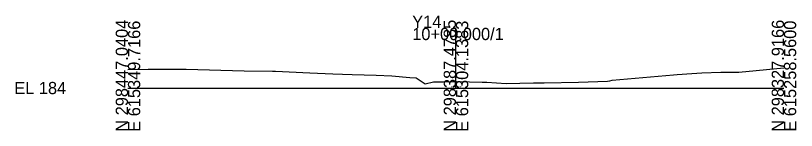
# Model space of a CAD drawing. Extents: x 517327 to 517505, y 114839 to 117370.
# Drawn here: x 517326.7 to 517505.2, y 114838.7 to 114864.9 of the extents above; entities that cross this region are included whole.
import ezdxf

# ---------------------------------------------------------------- set-up
doc = ezdxf.new("R2010")
doc.units = 0
for name, color, linetype in [('Exist XS Ground Line', 7, 'Continuous'), ('Old_Level_60', 7, 'Continuous'), ('Old_Level_63', 7, 'Continuous')]:
    doc.layers.add(name, color=color, linetype=linetype)

msp = doc.modelspace()

# ---------------------------------------------------------------- linework, layer by layer
at = {"layer": 'Exist XS Ground Line'}
for p, q in [((517492.08, 114851.95), (517502.36, 114852.95)), ((517352.36, 114852.6), (517357.02, 114852.65)), ((517357.02, 114852.65), (517362.06, 114852.68)), ((517362.06, 114852.68), (517365.68, 114852.65)), ((517365.68, 114852.65), (517378.94, 114852.27)), ((517378.94, 114852.27), (517385.42, 114852.23)), ((517385.42, 114852.23), (517386.07, 114852.21)), ((517386.07, 114852.21), (517393.92, 114851.84)), ((517393.92, 114851.84), (517399.21, 114851.6)), ((517399.21, 114851.6), (517403.62, 114851.45)), ((517403.62, 114851.45), (517409.1, 114851.27)), ((517409.1, 114851.27), (517412.73, 114851.13)), ((517412.73, 114851.13), (517416.78, 114850.77)), ((517463.07, 114850.13), (517477.08, 114851.37)), ((517477.08, 114851.37), (517477.97, 114851.48)), ((517477.97, 114851.48), (517481.33, 114851.66)), ((517481.33, 114851.66), (517483.55, 114851.84)), ((517483.55, 114851.84), (517487.91, 114851.99)), ((517487.91, 114851.99), (517492.08, 114851.95)), ((517416.78, 114850.77), (517418.29, 114850.66)), ((517418.29, 114850.66), (517418.7, 114850.38)), ((517418.7, 114850.38), (517420.33, 114849.35)), ((517420.33, 114849.35), (517422.2, 114849.8)), ((517422.2, 114849.8), (517424.46, 114849.77)), ((517424.46, 114849.77), (517427.51, 114849.84)), ((517427.51, 114849.84), (517430.48, 114849.76)), ((517430.48, 114849.76), (517433.36, 114849.71)), ((517433.36, 114849.71), (517433.71, 114849.68)), ((517433.71, 114849.68), (517434.4, 114849.66)), ((517434.4, 114849.66), (517438.83, 114849.36)), ((517438.83, 114849.36), (517445.1, 114849.53)), ((517445.1, 114849.53), (517446.59, 114849.55)), ((517446.59, 114849.55), (517447.51, 114849.51)), ((517447.51, 114849.51), (517455.41, 114849.72)), ((517455.41, 114849.72), (517461.98, 114849.95)), ((517461.98, 114849.95), (517462.57, 114850)), ((517462.57, 114850), (517463.07, 114850.13))]:
    msp.add_line(p, q, dxfattribs=at)
at = {"layer": 'Old_Level_63'}
for p, q in [((517427.36, 114848.36), (517427.36, 114862.12)), ((517352.36, 114848.36), (517427.36, 114848.36)), ((517427.36, 114848.36), (517502.36, 114848.36))]:
    msp.add_line(p, q, dxfattribs=at)

# ---------------------------------------------------------------- texts
at = {"layer": 'Old_Level_60'}
msp.add_text('185.476', height=0.5, dxfattribs=at).set_placement((517426.16, 114848.34))
at = {"layer": 'Old_Level_63'}
for s, p in [('N 298447.0404', (517352.36, 114838.37)), ('E 615349.7166', (517355.16, 114838.36)), ('N 298387.4785', (517427.36, 114838.36)), ('E 615304.1383', (517430.16, 114838.36)), ('N 298327.9166', (517502.36, 114838.36)), ('E 615258.5600', (517505.16, 114838.37))]:
    msp.add_text(s, height=2.8, rotation=90, dxfattribs=at).set_placement(p)
for s, p in [('Y14', (517417.36, 114862.12)), ('10+00.000/1', (517417.37, 114859.32)), ('EL 184', (517326.37, 114846.96))]:
    msp.add_text(s, height=2.8, dxfattribs=at).set_placement(p)

doc.saveas('drawing.dxf')
